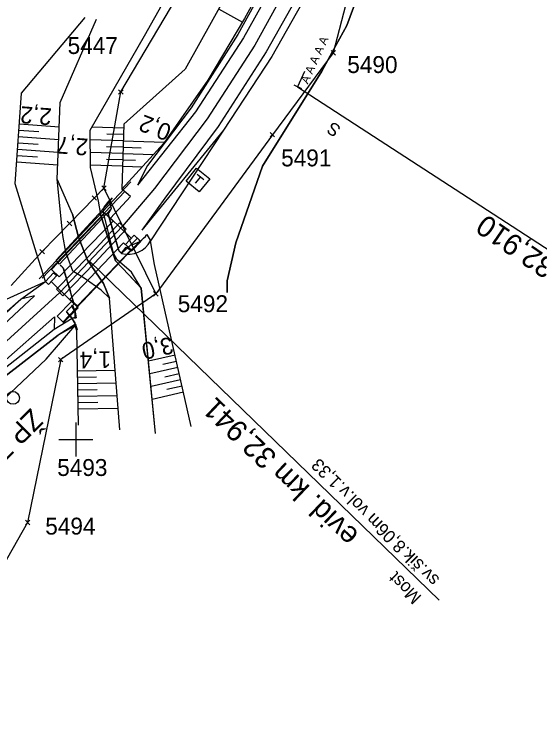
# Model space of a CAD drawing. Extents: x -804166 to -803706, y -1151030 to -1150147.
# Drawn here: x -803907.3 to -803845.1, y -1150734.2 to -1150649.7 of the extents above; entities that cross this region are included whole.
import ezdxf

# ---------------------------------------------------------------- set-up
doc = ezdxf.new("R2010")
doc.units = 0
for name, color, linetype in [('0381KM032-037P - Vrstva 1', 7, 'Continuous'), ('0381KM032-037P - Vrstva 13', 7, 'Continuous'), ('0381KM032-037P - Vrstva 17', 7, 'Continuous'), ('0381KM032-037P - Vrstva 18', 7, 'Continuous'), ('0381KM032-037P - Vrstva 33', 7, 'Continuous'), ('0381KM032-037P - Vrstva 35', 7, 'Continuous'), ('0381KM032-037P - Vrstva 4', 7, 'Continuous'), ('0381KM032-037P - Vrstva 48', 7, 'Continuous'), ('0381KM032-037P - Vrstva 49', 7, 'Continuous'), ('0381KM032-037P - Vrstva 50', 7, 'Continuous'), ('0381KM032-037P - Vrstva 55', 7, 'Continuous'), ('0381KM032-037P - Vrstva 6', 7, 'Continuous'), ('krizky_1000 - Vrstva 1', 7, 'Continuous'), ('szdc - hran DP', 7, 'Continuous'), ('szdc - szdc_cislo', 7, 'Continuous'), ('szdc - szdc_krizek', 7, 'Continuous'), ('vyt_sit - stávající', 7, 'Continuous')]:
    doc.layers.add(name, color=color, linetype=linetype)

msp = doc.modelspace()

# ---------------------------------------------------------------- linework, layer by layer
at = {"layer": '0381KM032-037P - Vrstva 1'}
msp.add_line((-803894.474, -1150674.768), (-803901.906, -1150682.605), dxfattribs=at)
for points in [[(-803862.645, -1150536.71), (-803860.057, -1150547.81), (-803858.364, -1150558.718), (-803857.51, -1150569.546), (-803857.425, -1150579.975), (-803858.096, -1150590.725), (-803859.58, -1150601.687), (-803861.73, -1150611.946), (-803864.691, -1150622.329), (-803868.306, -1150632.261), (-803873.118, -1150643.006), (-803878.784, -1150653.323), (-803884.455, -1150662.043), (-803890.68, -1150670.289), (-803894.474, -1150674.768)], [(-803901.906, -1150682.605), (-803910.014, -1150690), (-803918.643, -1150696.775), (-803928.041, -1150703.062), (-803937.946, -1150708.688), (-803946.795, -1150712.932), (-803956.655, -1150716.869), (-803966.853, -1150720.098), (-803973.694, -1150721.813), (-803983.505, -1150723.682), (-803993.918, -1150724.91), (-804004.459, -1150725.421), (-804014.948, -1150725.206), (-804025.475, -1150724.252), (-804035.41, -1150722.673), (-804044.081, -1150720.735), (-804054.774, -1150717.615), (-804061.472, -1150715.138)]]:
    msp.add_lwpolyline(points, dxfattribs=at)
at = {"layer": '0381KM032-037P - Vrstva 13'}
for p, q in [((-803900.427, -1150685.689), (-803900.743, -1150685.422)), ((-803900.427, -1150685.69), (-803902.54, -1150686.99)), ((-803900.02, -1150686.371), (-803900.089, -1150686.205)), ((-803900.019, -1150686.37), (-803902.092, -1150687.65))]:
    msp.add_line(p, q, dxfattribs=at)
for points in [[(-803900.743, -1150685.422), (-803900.692, -1150685.394), (-803900.742, -1150685.419)], [(-803900.02, -1150686.371), (-803899.851, -1150687.044), (-803899.848, -1150687.042), (-803900.019, -1150686.37), (-803900.427, -1150685.69), (-803900.742, -1150685.419)], [(-803900.089, -1150686.205), (-803900.081, -1150686.195), (-803900.317, -1150685.837), (-803900.317, -1150685.836), (-803900.427, -1150685.689)], [(-803902.54, -1150686.99), (-803908.533, -1150691.682), (-803917.537, -1150698.646), (-803926.885, -1150705.063), (-803937.003, -1150710.487), (-803946.017, -1150714.661), (-803956.263, -1150718.85), (-803966.288, -1150722.189), (-803972.538, -1150724.259)], [(-803972.286, -1150725.012), (-803966.125, -1150722.974), (-803955.955, -1150719.581), (-803945.709, -1150715.376), (-803936.565, -1150711.19), (-803926.506, -1150705.78), (-803917.073, -1150699.315), (-803908.044, -1150692.29), (-803902.092, -1150687.65)]]:
    msp.add_lwpolyline(points, dxfattribs=at)
at = {"layer": '0381KM032-037P - Vrstva 17'}
for p, q in [((-803903.995, -1150680.91), (-803894.145, -1150670.618)), ((-803892.37, -1150676.505), (-803901.521, -1150686.105))]:
    msp.add_line(p, q, dxfattribs=at)
for points in [[(-803867.911, -1150651.01), (-803864.194, -1150640.965), (-803863.34, -1150639.848), (-803860.107, -1150635.351), (-803857.384, -1150629.008), (-803845.634, -1150598.77), (-803839.769, -1150573.178), (-803837.289, -1150572.72)], [(-803882.068, -1150682.623), (-803882.094, -1150681.238), (-803881.038, -1150676.732), (-803877.877, -1150667.643), (-803870.889, -1150656.426), (-803869.632, -1150654.159), (-803867.911, -1150651.01)]]:
    msp.add_lwpolyline(points, dxfattribs=at)
at = {"layer": '0381KM032-037P - Vrstva 18'}
for p, q in [((-803902.321, -1150678.769), (-803895.977, -1150671.88)), ((-803895.96, -1150671.875), (-803897.006, -1150672.976)), ((-803895.972, -1150671.746), (-803896.032, -1150671.776)), ((-803895.788, -1150672.67), (-803901.935, -1150679.269)), ((-803896.656, -1150672.511), (-803897.006, -1150672.976)), ((-803895.788, -1150672.67), (-803895.788, -1150672.67)), ((-803895.902, -1150673.797), (-803893.451, -1150676.167)), ((-803895.155, -1150676.86), (-803895.737, -1150674.89)), ((-803892.742, -1150676.15), (-803892.333, -1150676.585)), ((-803891.585, -1150675.741), (-803891.14, -1150676.484)), ((-803893.531, -1150676.988), (-803894.581, -1150678.003)), ((-803892.333, -1150676.585), (-803893.36, -1150677.66)), ((-803892.31, -1150676.591), (-803892.333, -1150676.585)), ((-803893.36, -1150677.66), (-803893.335, -1150677.645)), ((-803901.935, -1150679.269), (-803902.321, -1150678.769)), ((-803856.973, -1150719.009), (-803898.348, -1150678.956)), ((-803900.514, -1150683.661), (-803902.936, -1150681.284)), ((-803900.594, -1150682.547), (-803901.206, -1150680.55)), ((-803900.177, -1150683.94), (-803901.093, -1150684.85)), ((-803900.181, -1150683.948), (-803900.177, -1150683.94)), ((-803899.733, -1150684.407), (-803899.765, -1150684.362)), ((-803900.692, -1150685.394), (-803901.461, -1150686.142)), ((-803900.692, -1150685.394), (-803901.093, -1150684.85)), ((-803900.087, -1150684.927), (-803900.086, -1150684.886)), ((-803900.387, -1150685.649), (-803899.968, -1150685.591))]:
    msp.add_line(p, q, dxfattribs=at)
for points in [[(-803895.902, -1150673.797), (-803893.509, -1150671.262), (-803894.538, -1150670.386)], [(-803892.244, -1150682.081), (-803893.405, -1150680.212), (-803895.1, -1150678.76), (-803895.543, -1150677.939), (-803896.702, -1150673.136), (-803896.656, -1150672.511), (-803896.032, -1150671.776)], [(-803894.595, -1150677.949), (-803894.892, -1150677.628), (-803896.154, -1150673.353), (-803896.156, -1150673.313), (-803895.788, -1150672.67), (-803896.032, -1150671.776), (-803895.682, -1150671.402), (-803895.972, -1150671.746), (-803895.977, -1150671.88)], [(-803896.154, -1150673.353), (-803895.788, -1150672.67), (-803895.977, -1150671.88)], [(-803895.96, -1150671.875), (-803896.006, -1150671.732), (-803896.032, -1150671.776)], [(-803902.876, -1150679.904), (-803896.545, -1150673.237), (-803895.586, -1150674.167), (-803901.958, -1150680.766), (-803902.876, -1150679.904)], [(-803896.156, -1150673.313), (-803894.92, -1150677.658), (-803894.581, -1150678.003)], [(-803902.301, -1150682.211), (-803901.541, -1150682.984), (-803897.786, -1150679.126), (-803894.042, -1150675.093), (-803894.835, -1150674.357), (-803898.482, -1150678.342), (-803902.301, -1150682.211)], [(-803892.31, -1150676.591), (-803893.094, -1150675.842), (-803894.104, -1150676.91), (-803893.335, -1150677.645), (-803892.31, -1150676.591)], [(-803892.742, -1150676.15), (-803892.697, -1150676.16), (-803893.531, -1150676.988)], [(-803900.704, -1150683.386), (-803899.78, -1150684.198), (-803893.446, -1150677.55), (-803894.353, -1150676.739), (-803900.704, -1150683.386)], [(-803894.581, -1150678.003), (-803894.595, -1150677.949), (-803894.041, -1150677.229), (-803894.041, -1150677.229), (-803893.36, -1150677.66)], [(-803901.935, -1150679.269), (-803901.931, -1150679.271), (-803902.334, -1150678.769), (-803902.321, -1150678.769)], [(-803900.181, -1150683.948), (-803901.502, -1150679.684), (-803901.835, -1150679.365), (-803901.815, -1150679.357), (-803901.461, -1150679.762), (-803900.212, -1150683.983), (-803900.181, -1150683.948)], [(-803902.232, -1150680.579), (-803903.222, -1150681.645), (-803903.605, -1150681.318), (-803902.621, -1150680.279), (-803902.232, -1150680.579)], [(-803899.765, -1150684.362), (-803901.461, -1150686.142), (-803902.204, -1150685.415), (-803900.514, -1150683.661), (-803899.765, -1150684.362)], [(-803901.093, -1150684.85), (-803901.09, -1150684.852), (-803900.467, -1150684.209), (-803900.408, -1150684.126), (-803900.086, -1150684.886), (-803899.968, -1150685.591), (-803900.061, -1150685.507), (-803900.087, -1150684.927), (-803900.467, -1150684.209)], [(-803900.177, -1150683.94), (-803899.733, -1150684.407), (-803900.692, -1150685.394)], [(-803901.09, -1150684.852), (-803900.387, -1150685.649), (-803900.061, -1150685.507)]]:
    msp.add_lwpolyline(points, dxfattribs=at)
for centre, major_axis, ratio, start_param, end_param in [((-803893.838, -1150674.452), (2.475, 1.269), 0.908828, 4.38934, 5.247205), ((-803893.887, -1150674.932), (1.395, -2.862), 0.971802, 5.593201, 6.899505)]:
    msp.add_ellipse(centre, major_axis=major_axis, ratio=ratio, start_param=start_param, end_param=end_param, dxfattribs=at)
at = {"layer": '0381KM032-037P - Vrstva 33'}
for p, q in [((-803885.617, -1150668.595), (-803884.838, -1150669.222)), ((-803885.227, -1150668.909), (-803885.855, -1150669.687))]:
    msp.add_line(p, q, dxfattribs=at)
msp.add_lwpolyline([(-803885.693, -1150667.892), (-803884.135, -1150669.146), (-803885.389, -1150670.704), (-803886.947, -1150669.45), (-803885.693, -1150667.892)], dxfattribs=at)
at = {"layer": '0381KM032-037P - Vrstva 35'}
msp.add_line((-803904.333, -1150681.001), (-803893.471, -1150669.506), dxfattribs=at)
at = {"layer": '0381KM032-037P - Vrstva 4'}
for points in [[(-803862.041, -1150601.171), (-803863.934, -1150611.478), (-803866.955, -1150621.666), (-803870.636, -1150631.623), (-803875.322, -1150642.112), (-803880.813, -1150652.073), (-803886.36, -1150660.761), (-803891.5, -1150667.581), (-803892.695, -1150669.921)], [(-803861.107, -1150601.386), (-803863.249, -1150611.592), (-803866.278, -1150621.841), (-803869.683, -1150631.826), (-803874.548, -1150642.393), (-803880.159, -1150652.477), (-803885.847, -1150661.208), (-803892.695, -1150669.921)], [(-803858.016, -1150602.009), (-803860.157, -1150612.315), (-803863.229, -1150623.106), (-803866.722, -1150632.775), (-803871.621, -1150643.742), (-803877.472, -1150654.13), (-803883.137, -1150662.978), (-803889.477, -1150671.458), (-803892.178, -1150675.246)], [(-803857.109, -1150602.102), (-803859.611, -1150612.518), (-803862.49, -1150623.34), (-803866.1, -1150633.182), (-803870.873, -1150644.181), (-803876.806, -1150654.687), (-803882.51, -1150663.405), (-803892.178, -1150675.246)], [(-803904.886, -1150683.001), (-803906.516, -1150683.391), (-803911.518, -1150688.069), (-803920.109, -1150694.835), (-803929.412, -1150700.935), (-803939.155, -1150706.209), (-803947.889, -1150710.398), (-803957.601, -1150714.533), (-803967.413, -1150717.637)], [(-803904.886, -1150683.001), (-803911.05, -1150688.735), (-803919.705, -1150695.384), (-803929.087, -1150701.477), (-803938.787, -1150707.105), (-803947.481, -1150711.337), (-803957.418, -1150715.321), (-803967.176, -1150718.433)], [(-803902.503, -1150685.469), (-803908.943, -1150691.185), (-803917.694, -1150697.991), (-803927.241, -1150704.348), (-803937.195, -1150710.055), (-803946.246, -1150714.302), (-803956.405, -1150718.419), (-803966.448, -1150721.526)], [(-803902.503, -1150685.469), (-803902.54, -1150686.99), (-803908.533, -1150691.682), (-803917.537, -1150698.646), (-803926.885, -1150705.063), (-803937.003, -1150710.487), (-803946.017, -1150714.661), (-803956.263, -1150718.85), (-803966.288, -1150722.189)]]:
    msp.add_lwpolyline(points, dxfattribs=at)
at = {"layer": '0381KM032-037P - Vrstva 48'}
for p, q in [((-803883.093, -1150649.037), (-803880.278, -1150650.604)), ((-803906.68, -1150662.653), (-803901.962, -1150662.988)), ((-803906.733, -1150663.401), (-803904.362, -1150663.569)), ((-803894.338, -1150663.165), (-803898.097, -1150663.061)), ((-803906.786, -1150664.149), (-803902.02, -1150664.487)), ((-803894.358, -1150663.915), (-803896.337, -1150663.86)), ((-803906.84, -1150664.897), (-803904.445, -1150665.067)), ((-803894.379, -1150664.664), (-803898.309, -1150664.555)), ((-803894.379, -1150664.664), (-803889.482, -1150664.8)), ((-803906.893, -1150665.645), (-803902.079, -1150665.987)), ((-803894.421, -1150666.164), (-803898.295, -1150666.056)), ((-803894.4, -1150665.414), (-803896.351, -1150665.36)), ((-803894.4, -1150665.414), (-803892.261, -1150665.473)), ((-803906.946, -1150666.394), (-803904.527, -1150666.565)), ((-803894.442, -1150666.913), (-803896.365, -1150666.86)), ((-803894.442, -1150666.913), (-803892.948, -1150666.955)), ((-803894.421, -1150666.164), (-803890.788, -1150666.265)), ((-803906.999, -1150667.142), (-803902.138, -1150667.487)), ((-803894.462, -1150667.663), (-803898.28, -1150667.557)), ((-803894.462, -1150667.663), (-803892.12, -1150667.728)), ((-803888.25, -1150690.03), (-803891.388, -1150690.739)), ((-803888.085, -1150690.761), (-803889.7, -1150691.126)), ((-803899.836, -1150691.878), (-803895.322, -1150691.802)), ((-803887.92, -1150691.493), (-803891.24, -1150692.243)), ((-803887.754, -1150692.224), (-803889.46, -1150692.61)), ((-803899.823, -1150692.628), (-803897.543, -1150692.589)), ((-803887.589, -1150692.956), (-803891.092, -1150693.748)), ((-803899.81, -1150693.378), (-803895.204, -1150693.3)), ((-803887.424, -1150693.688), (-803889.221, -1150694.094)), ((-803899.798, -1150694.128), (-803897.472, -1150694.088)), ((-803899.785, -1150694.878), (-803895.086, -1150694.798)), ((-803887.258, -1150694.419), (-803890.945, -1150695.252)), ((-803899.772, -1150695.628), (-803897.4, -1150695.587)), ((-803899.76, -1150696.377), (-803894.968, -1150696.296))]:
    msp.add_line(p, q, dxfattribs=at)
at = {"layer": '0381KM032-037P - Vrstva 49'}
for p, q in [((-803882.51, -1150663.405), (-803891.14, -1150676.484)), ((-803900.099, -1150686.57), (-803902.092, -1150687.65))]:
    msp.add_line(p, q, dxfattribs=at)
for points in [[(-803855.009, -1150569.422), (-803855.013, -1150580.14), (-803855.681, -1150591.137), (-803857.109, -1150602.102), (-803859.611, -1150612.518), (-803862.49, -1150623.34), (-803866.1, -1150633.182), (-803870.873, -1150644.181), (-803876.806, -1150654.687), (-803882.51, -1150663.405)], [(-803867.826, -1150615.469), (-803873.958, -1150632.621), (-803887.064, -1150656.172), (-803894.324, -1150662.675), (-803894.538, -1150670.386)], [(-803865.684, -1150616.069), (-803868.473, -1150625.045), (-803871.506, -1150633.468), (-803875.458, -1150641.91), (-803880.036, -1150650.199), (-803884.384, -1150657.469), (-803889.567, -1150664.922), (-803894.538, -1150670.386)], [(-803879.144, -1150629.624), (-803891.889, -1150652.288), (-803898.32, -1150663.448), (-803898.278, -1150667.796), (-803897.353, -1150671.802), (-803897.063, -1150673.395), (-803895.285, -1150678.85), (-803893.718, -1150680.524), (-803892.244, -1150682.081)], [(-803857.384, -1150629.008), (-803860.107, -1150635.351), (-803863.34, -1150639.848), (-803864.194, -1150640.965), (-803867.911, -1150651.01), (-803869.632, -1150654.159), (-803870.889, -1150656.426), (-803877.877, -1150667.643), (-803881.038, -1150676.732), (-803882.094, -1150681.238), (-803882.068, -1150682.623)], [(-803903.605, -1150681.318), (-803904.65, -1150677.954), (-803907.183, -1150669.738), (-803906.423, -1150659.026), (-803898.899, -1150650.067)], [(-803902.205, -1150669.209), (-803901.85, -1150660.131), (-803897.556, -1150650.259)], [(-803882.094, -1150681.238), (-803881.038, -1150676.732), (-803877.877, -1150667.643), (-803870.889, -1150656.426), (-803869.632, -1150654.159), (-803867.911, -1150651.01)], [(-803895.993, -1150683.294), (-803896.707, -1150681.538), (-803898.609, -1150678.776), (-803899.692, -1150676.05), (-803900.386, -1150673.352), (-803902.205, -1150669.209)], [(-803895.993, -1150683.294), (-803897.012, -1150682.314), (-803899.014, -1150680.911), (-803900.346, -1150680.09), (-803901.19, -1150677.817), (-803901.54, -1150675.88), (-803902.205, -1150669.209)], [(-803886.343, -1150698.471), (-803890.675, -1150679.297), (-803891.14, -1150676.484)], [(-803984.817, -1150721.442), (-803974.636, -1150719.233), (-803973.09, -1150718.927), (-803972.805, -1150718.807), (-803972.246, -1150718.741), (-803965.21, -1150716.746), (-803957.601, -1150714.533), (-803947.889, -1150710.398), (-803939.155, -1150706.209), (-803931.831, -1150702.119), (-803924.086, -1150697.218), (-803916.608, -1150691.841), (-803910.081, -1150686.51), (-803906.516, -1150683.391), (-803903.605, -1150681.318)], [(-803972.246, -1150718.741), (-803965.841, -1150714.337), (-803956.596, -1150711.219), (-803948.841, -1150707.727), (-803941.393, -1150704.085), (-803932.776, -1150700.061), (-803925.787, -1150694.954), (-803918.146, -1150689.679), (-803911.549, -1150684.903), (-803903.605, -1150681.318)], [(-803890.546, -1150699.304), (-803892.24, -1150682.08)], [(-803894.766, -1150698.862), (-803895.993, -1150683.294)], [(-803973.24, -1150730.36), (-803966.718, -1150727.463), (-803955.163, -1150723.59), (-803942.536, -1150718.416), (-803927.909, -1150711.458), (-803917.773, -1150704.055), (-803910.649, -1150697.212), (-803903.52, -1150690.487), (-803900.099, -1150686.57)], [(-803900.099, -1150686.57), (-803899.917, -1150687.085), (-803899.727, -1150698.309)], [(-803902.092, -1150687.65), (-803908.044, -1150692.29), (-803917.073, -1150699.315), (-803926.506, -1150705.78), (-803936.565, -1150711.19), (-803945.709, -1150715.376), (-803955.955, -1150719.581), (-803966.125, -1150722.974), (-803972.286, -1150725.012), (-803974.7, -1150725.768), (-803983.368, -1150727.37), (-803993.836, -1150727.905), (-804004.989, -1150728.615), (-804004.868, -1150729.928), (-804012.985, -1150730.258), (-804018.762, -1150729.808), (-804029.792, -1150728.642), (-804054.152, -1150723.147), (-804060.274, -1150720.943)]]:
    msp.add_lwpolyline(points, dxfattribs=at)
at = {"layer": '0381KM032-037P - Vrstva 50'}
for points in [[(-803870.937, -1150611.902), (-803879.144, -1150629.624), (-803891.889, -1150652.288), (-803898.32, -1150663.448), (-803898.278, -1150667.796), (-803897.353, -1150671.802), (-803897.063, -1150673.395)], [(-803900.386, -1150673.352), (-803902.205, -1150669.209), (-803901.85, -1150660.131), (-803897.556, -1150650.259)], [(-803900.386, -1150673.352), (-803899.692, -1150676.05), (-803898.609, -1150678.776), (-803896.707, -1150681.538), (-803895.993, -1150683.294)], [(-803892.24, -1150682.08), (-803893.718, -1150680.524), (-803895.285, -1150678.85), (-803897.063, -1150673.395)], [(-803890.546, -1150699.304), (-803892.244, -1150682.081)], [(-803894.766, -1150698.862), (-803895.993, -1150683.294)]]:
    msp.add_lwpolyline(points, dxfattribs=at)
at = {"layer": '0381KM032-037P - Vrstva 55'}
msp.add_line((-803896.67, -1150670.26), (-803890.53, -1150682.77), dxfattribs=at)
at = {"layer": '0381KM032-037P - Vrstva 6'}
for p, q in [((-803872.924, -1150656.457), (-803873.746, -1150658.258)), ((-803874.201, -1150658.05), (-803873.291, -1150658.466)), ((-803873.746, -1150658.258), (-803837.626, -1150681.738))]:
    msp.add_line(p, q, dxfattribs=at)
at = {"layer": 'krizky_1000 - Vrstva 1'}
for points in [[(-803900, -1150698), (-803900, -1150702)], [(-803902, -1150700), (-803898, -1150700)]]:
    msp.add_lwpolyline(points, dxfattribs=at)
at = {"layer": 'szdc - hran DP'}
for p, q in [((-803894.67, -1150658.87), (-803877.2, -1150629.46)), ((-803866.11, -1150640.84), (-803869.51, -1150654.24)), ((-803869.51, -1150654.24), (-803876.72, -1150663.94)), ((-803896.67, -1150670.26), (-803894.67, -1150658.87)), ((-803876.72, -1150663.94), (-803890.53, -1150682.77)), ((-803897.8, -1150671.42), (-803896.67, -1150670.26)), ((-803900.74, -1150674.44), (-803897.8, -1150671.42)), ((-803903.98, -1150677.77), (-803900.74, -1150674.44)), ((-803907.67, -1150681.78), (-803903.98, -1150677.77)), ((-803890.53, -1150682.77), (-803901.78, -1150690.55)), ((-803901.78, -1150690.55), (-803905.7, -1150709.82)), ((-803905.7, -1150709.82), (-803919.68, -1150734.23))]:
    msp.add_line(p, q, dxfattribs=at)
at = {"layer": 'szdc - szdc_krizek'}
for p, q in [((-803869.245, -1150654.505), (-803869.776, -1150653.975)), ((-803869.776, -1150654.505), (-803869.245, -1150653.975)), ((-803894.405, -1150659.135), (-803894.936, -1150658.605)), ((-803894.936, -1150659.135), (-803894.405, -1150658.605)), ((-803876.455, -1150664.205), (-803876.986, -1150663.675)), ((-803876.986, -1150664.205), (-803876.455, -1150663.675)), ((-803896.405, -1150670.525), (-803896.936, -1150669.995)), ((-803896.936, -1150670.525), (-803896.405, -1150669.995)), ((-803897.535, -1150671.685), (-803898.066, -1150671.155)), ((-803898.066, -1150671.685), (-803897.535, -1150671.155)), ((-803900.475, -1150674.705), (-803901.006, -1150674.175)), ((-803901.006, -1150674.705), (-803900.475, -1150674.175)), ((-803903.715, -1150678.035), (-803904.246, -1150677.505)), ((-803904.246, -1150678.035), (-803903.715, -1150677.505)), ((-803890.265, -1150683.035), (-803890.796, -1150682.505)), ((-803890.796, -1150683.035), (-803890.265, -1150682.505)), ((-803901.515, -1150690.815), (-803902.046, -1150690.285)), ((-803902.046, -1150690.815), (-803901.515, -1150690.285)), ((-803905.435, -1150710.085), (-803905.966, -1150709.555)), ((-803905.966, -1150710.085), (-803905.435, -1150709.555))]:
    msp.add_line(p, q, dxfattribs=at)
at = {"layer": 'vyt_sit - stávající'}
msp.add_circle((-803907.43, -1150695.075), 0.756, dxfattribs=at)

# ---------------------------------------------------------------- texts
at = {"layer": '0381KM032-037P - Vrstva 18'}
for s, height, rotation, p in [('evid. km 32,941', 2.5, 136.38556, (-803866.362, -1150711.135)), ('sv.šik.8,06m vol.v.1,33', 1.5, 134.97726, (-803856.852, -1150716.475)), ('Most', 1.5, 134.97726, (-803858.974, -1150718.595))]:
    msp.add_text(s, height=height, rotation=rotation, dxfattribs=at).set_placement(p)
at = {"layer": '0381KM032-037P - Vrstva 48'}
for s, rotation, p in [('2,2', 175.94175, (-803902.788, -1150660.827)), ('0,2', 158.4103, (-803888.52, -1150662.876)), ('2,7', 175.55344, (-803898.475, -1150664.424)), ('3,0', 192.73114, (-803888.718, -1150687.818)), ('1,4', 180.96981, (-803895.839, -1150689.546))]:
    msp.add_text(s, height=2, rotation=rotation, dxfattribs=at).set_placement(p)
at = {"layer": '0381KM032-037P - Vrstva 6'}
for s, height, rotation, p in [('  A A A A A ', 1, 65.47944, (-803872.836, -1150658.673)), ('S', 1.5, 146.15257, (-803868.497, -1150663.067)), ('km 32,910', 2.5, 145.47944, (-803838.584, -1150682.1))]:
    msp.add_text(s, height=height, rotation=rotation, dxfattribs=at).set_placement(p)
at = {"layer": 'szdc - szdc_cislo'}
for s, p in [('5447', (-803900.967, -1150654.381)), ('5490', (-803867.859, -1150656.634)), ('5491', (-803875.689, -1150667.681)), ('5492', (-803887.929, -1150684.933)), ('5493', (-803902.202, -1150704.319)), ('5494', (-803903.615, -1150711.256))]:
    msp.add_text(s, height=2, dxfattribs=at).set_placement(p)
at = {"layer": 'vyt_sit - stávající'}
msp.add_text('ŽP 758', height=2.4, rotation=225, dxfattribs=at).set_placement((-803905.333, -1150696.219))

doc.saveas('drawing.dxf')
